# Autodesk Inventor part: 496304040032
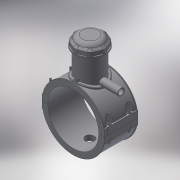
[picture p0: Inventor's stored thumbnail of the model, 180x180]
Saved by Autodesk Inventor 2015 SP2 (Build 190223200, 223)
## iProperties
Created: 2017-07
Part Number: 496304040032
Material: Generic
Description: PLASSON TAPPING SADDLE 40x32
Document SubType Name: Modeling
Designer: KIM
Mass: 144.515 g
Surface Area: 707.426 cm^2
Volume: 144.515 cm^3
Density: 1 g/cm^3
Appearance: Default
Author: KIM
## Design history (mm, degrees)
derived "496304.ipt"
feature "Solid1::496304.ipt"
feature "Solid2::496304.ipt"
feature "Solid4::496304.ipt"
feature "Solid5::496304.ipt"
tag "TaggingFeature1"
body "Solid1"
body "Solid2"
other parameters: "B_" = 66, "d_t" = 6, "H_2" = 94, "H_1" = 11, "d_1" = 32, "H_" = 121, "d1" = 52, "d148" = 0.6, "d160" = 0.6, "d169" = 3.375, "d192" = 6.3, "d2" = 66, "d5" = 0, "d6" = 0.1, "d8" = 0, "d19" = 6, "d20" = 6, "d23" = 0, "d26" = 0, "d29" = 3, "d30" = 13.33333, "d31" = 6, "d32" = 0, "d33" = 0, "d34" = 0.6, "d40" = 27.04, "d41" = 38, "d43" = 0, "d45" = 0, "d47" = 86, "d70" = 15, "d72" = 0, "d73" = 6, "d75" = 5, "d76" = 0, "d77" = 2, "d79" = 15, "d82" = 5 deg, "d84" = 4, "d85" = 14, "d86" = 0, "d87" = 3, "d88" = 0, "d89" = 1, "d90" = 1, "d92" = 0, "d93" = 0.5, "d94" = 21.05263, "d96" = 53.04, "d97" = 2, "d98" = 0, "d102" = 0.4, "d120" = 140 deg, "d121" = 24.228, "d122" = 20 deg, "d123" = 104, "d124" = 31.2, "d126" = 0, "d143" = 41.2, "d145" = 9.23077, "d149" = 0.6, "d150" = 10.15385, "d154" = 0, "d156" = 26, "d157" = 160 deg, "d159" = 2.4, "d161" = 0.6, "d163" = 0, "d167" = 4, "d168" = 25.36585, "d170" = 3.375, "d172" = 0, "d173" = 1, "d176" = 20 deg, "d177" = 2.8, "d178" = 12, "d180" = 0, "d183" = 4.8, "d184" = 2.24, "d185" = 32.5, "d186" = 32.5, "d187" = 26, "d188" = 3.6, "d189" = 2.8, "d190" = 0, "d191" = 39, "d193" = 6.3, "d194" = 3.5, "d195" = 90 deg, "d197" = 0, "d199" = 0, "d200" = 6, "d202" = 0, "d203" = 94, "d204" = 36.1, "d205" = 26.6, "d206" = 32.3, "d207" = 70.5, "d208" = 73.32, "d209" = 87.42, "d210" = 32.68, "d211" = 38, "d212" = 30.4, "d213" = -4.5, "d216" = 0, "d217" = 4, "d218" = 4, "d219" = 0.8, "d224" = 0, "d230" = 2.4, "d233" = 6, "d236" = 33, "d238" = 6.02433, "d243" = 6, "d247" = 6, "d248" = 6, "d249" = 6, "d253" = 6, "d254" = 6, "d256" = 6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
